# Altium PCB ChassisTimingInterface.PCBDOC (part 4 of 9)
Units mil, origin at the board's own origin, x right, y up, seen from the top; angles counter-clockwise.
Board outline 7007.87 x 4368.85 mil, 10 copper layers (Top Layer, Int1 (GND), Int2 (Sign), Int3 (Sign), Int4 (PWR), Int5 (GND), Int6 (Sign), Int7 (Sign), Int8 (GND), Bottom Layer), stack 54.89 mil thick; 537 components, 525 nets, 2288 pads, 1306 vias.
Unrouted connection lines stored in the file: 373.
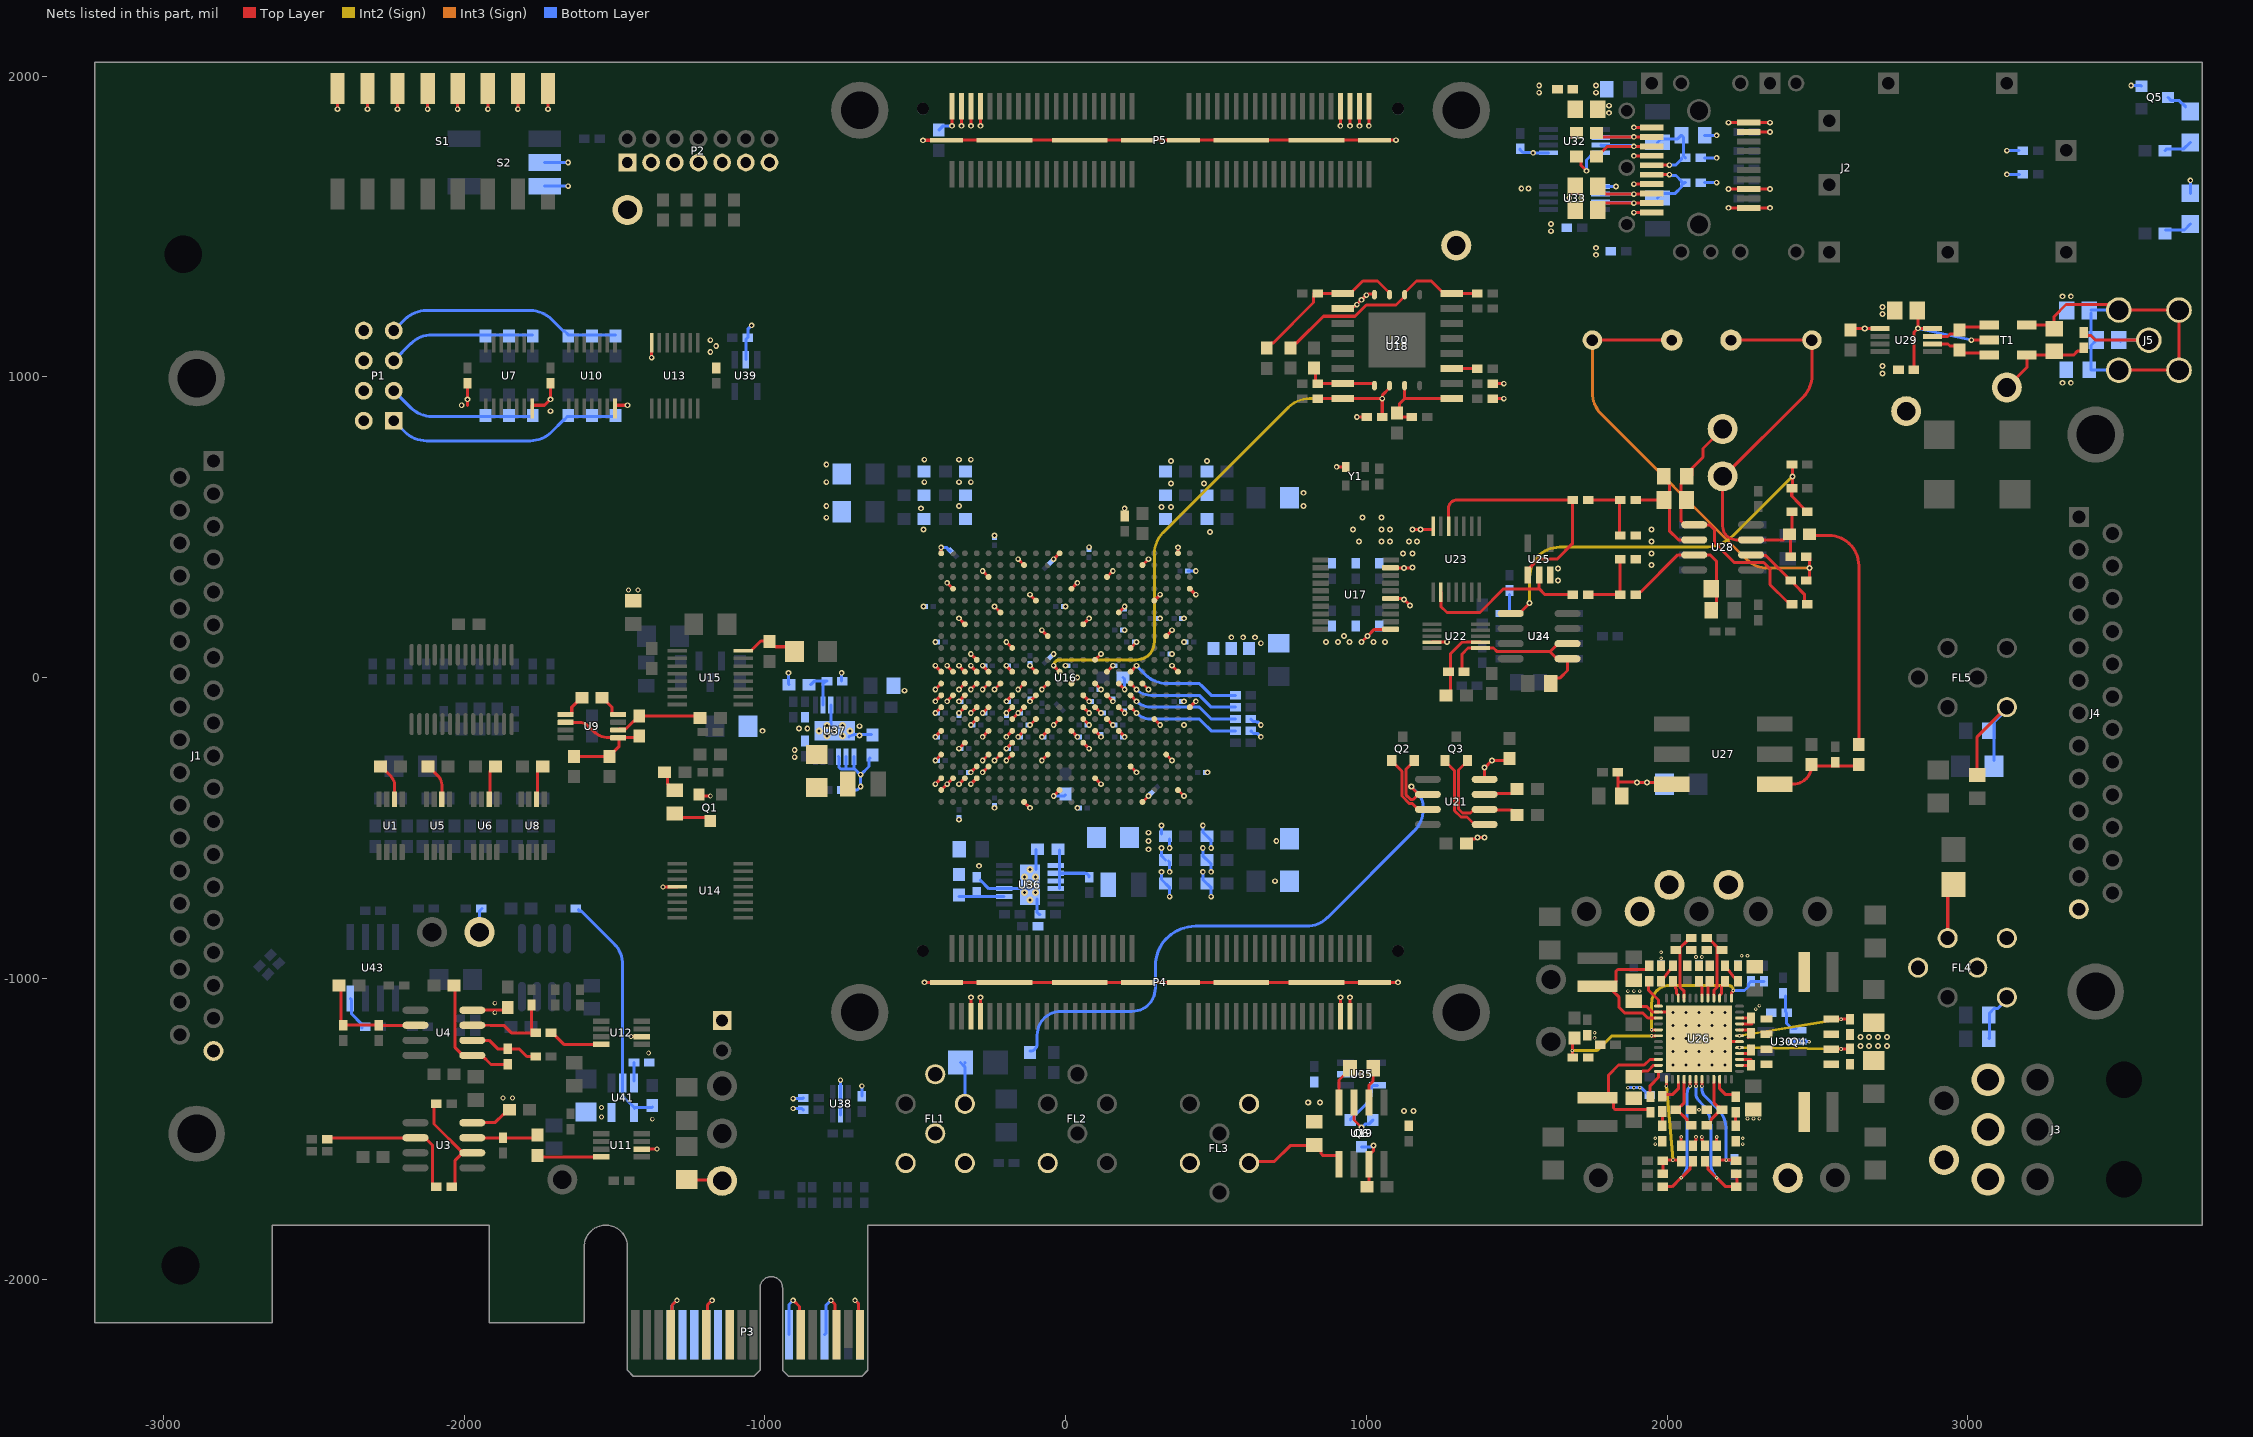
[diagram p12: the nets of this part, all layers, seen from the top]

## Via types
v1: diameter 19, hole 10, Top Layer to Bottom Layer, tented both sides, 667 vias
v2: diameter 20, hole 10, Top Layer to Bottom Layer, tented both sides, 248 vias
v3: diameter 16, hole 10, Top Layer to Bottom Layer, tented both sides, 191 vias
v4: diameter 12, hole 6, Top Layer to Bottom Layer, tented both sides, 85 vias
v5: diameter 19.68, hole 10, Top Layer to Bottom Layer, tented both sides, 50 vias
v6: diameter 17.72, hole 10, Top Layer to Bottom Layer, tented both sides, 19 vias
v7: diameter 19, hole 10, Top Layer to Bottom Layer, 15 vias
v8: diameter 23.62, hole 10, Top Layer to Bottom Layer, tented both sides, 14 vias
v9: diameter 20, hole 10, Top Layer to Bottom Layer, 11 vias
v10: diameter 16, hole 10, Top Layer to Bottom Layer, 3 vias
v11: diameter 22, hole 12, Top Layer to Bottom Layer, tented both sides, 2 vias
v12: diameter 19.02, hole 10, Top Layer to Bottom Layer, tented both sides, 1 vias

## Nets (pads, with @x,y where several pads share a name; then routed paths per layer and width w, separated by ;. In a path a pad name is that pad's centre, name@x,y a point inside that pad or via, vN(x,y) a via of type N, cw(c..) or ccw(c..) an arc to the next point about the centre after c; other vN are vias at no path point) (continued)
GND: C6.2 C12.2 C18.2 C23.2 C25.1 C26.1 C28.2 C29.2 C31.1 C32.1 C35.1 C37.1 C40.1 C41.2 C42.1 C43.2 C44.2 C45.1 C46.1 C51.1 C52.1 C53.2 C54.1 C57.1 C58.1 C59.2 C60.2 C68.2 C69.2 C70.1 C71.1 C74.2 C75.1 C76.2 C77.1 C78.2 C79.2 C80.2 C81.2 C84.1 C85.1 C86.1 C87.1 C88.1 C90.1 C92.1 C94.1 C95.1 C96.1 C97.1 C98.1 C99.1 C100.1 C101.1 C102.1 C103.1 C104.1 C105.1 C106.1 C107.1 C108.1 C109.1 C110.1 C111.1 C112.1 C113.1 C114.1 C115.1 C116.1 C117.1 C118.1 C119.1 C120.1 C121.1 C122.1 C123.1 C124.1 C125.1 C126.1 C127.1 C128.1 C129.1 C130.1 C131.2 C132.1 C133.2 C134.1 C135.2 C136.1 C137.1 C138.2 C139.2 C140.2 C141.1 C142.1 C143.1 C144.2 C145.2 C146.1 C147.1 C149.1 C150.1 C151.1 C152.1 C153.2 C155.1 C156.1 C157.2 C158.2 C159.2 C160.1 C161.1 C162.2 C163.2 C164.1 C165.1 C166.1 C167.1 C168.1 C169.2 C170.1 C171.1 C172.1 C173.2 C174.1 C175.2 C176.1 C177.1 C178.1 C179.1 C180.1 C181.1 C182.1 C183.1 C184.1 C185.1 C186.1 C187.1 C188.1 C189.1 C190.1 C191.1 C192.1 C195.2 C196.2 C197.1 C200.1 DS2.1 FL1.3 FL1.4 FL1.5 FL1.6 FL2.3 FL3.3 FL4.3 FL4.4 FL4.5 FL4.6 FL5.3 FR4.1 J1.19 J2.1 J2.3 J2.9 J2.10 J2.11 J2.14 J2.17 J2.20 J3.4 J3.5 J3.6 J4.13 P1.2 P1.4 P1.6 P1.8 P2.1 P2.3 P2.5 P2.7 P2.9 P2.11 P2.13 P3.A4 P3.A12 P3.A15 P3.A18 P3.B4 P3.B7 P3.B13 P3.B16 P3.B18 P4.5 P4.7 P4.73 P4.75 P4.81 P4.82 P4.83 P4.84 P4.85 P4.86 P4.87 P4.88 P5.2 P5.4 P5.6 P5.8 P5.74 P5.76 P5.78 P5.80 P5.81 P5.82 P5.83 P5.84 P5.85 P5.86 P5.87 P5.88 Q1.2 Q4.1 Q4.3 Q5.2 Q6.2 R28.2 R36.2 R45.2 R52.2 R53.2 R54.1 R57.2 R69.2 R70.2 R71.2 R73.1 R74.2 R75.2 R76.2 R80.2 R81.2 R93.2 R94.2 R98.2 R106.2 R107.2 R115.1 R116.1 R120.2 R123.1 R125.1 R127.1 R132.2 R133.2 R138.1 R139.1 R144.1 R147.1 R150.1 R151.1 R152.1 S1.1 S1.2 S1.3 S1.4 S1.5 S1.6 S1.7 S1.8 S2.3 S2.5 TP4.1 TP8.1 TP13.1 TP14.1 TP18.1 TP20.1 TP23.1 TP24.1 U7.7 U10.7 U11.6 U12.6 U13.7 U14.12 U16.A2 U16.A3 U16.A5 U16.A7 U16.A9 U16.A10 U16.A11 U16.A12 U16.A22 U16.AA2 U16.AA12 U16.AA22 U16.AB9 U16.AB19 U16.B3 U16.B10 U16.B12 U16.B19 U16.C3 U16.C6 U16.C9 U16.C10 U16.C11 U16.C12 U16.C16 U16.D3 U16.D4 U16.D8 U16.D9 U16.D11 U16.D12 U16.D13 U16.E4 U16.E5 U16.E7 U16.E9 U16.E11 U16.E12 U16.E20 U16.F5 U16.F11 U16.F17 U16.G5 U16.G6 U16.G7 U16.G8 U16.G9 U16.G10 U16.G12 U16.G14 U16.H1 U16.H7 U16.H9 U16.H11 U16.H21 U16.J8 U16.J10 U16.J12 U16.J18 U16.K5 U16.K7 U16.K11 U16.K15 U16.L2 U16.L8 U16.L22 U16.M7 U16.M11 U16.M19 U16.N6 U16.N8 U16.N9 U16.N10 U16.N16 U16.P3 U16.P7 U16.P9 U16.P11 U16.P13 U16.R8 U16.R10 U16.R12 U16.R20 U16.T7 U16.T9 U16.T11 U16.T17 U16.U4 U16.U14 U16.V1 U16.V11 U16.V21 U16.W8 U16.W18 U16.Y5 U16.Y15 U17.11 U17.15 U17.19 U18.10 U19.3 U20.4 U21.4 U22.9 U23.7 U25.3 U26.2 U26.11 U26.30 U26.49 U29.5 U30.2 U32.5 U33.5 U35.2 U36.9 U36.13 U37.9 U37.13 U38.2 U38.5 U39.2 W1.1 Y1.2 | length 14427.8
  Top Layer w10: v1(-2420.87,1889.76) S1.8@-2420.87,1958.66 ; v1(-2320.87,1889.76) S1.7@-2320.87,1958.66 ; v1(-2220.87,1889.76) S1.6@-2220.87,1958.66 ; v1(-2120.87,1889.76) S1.5@-2120.87,1958.66 ; v1(-2020.87,1889.76) S1.4@-2020.87,1958.66 ; -1988.19,905.51 C6.2@-1988.19,964.57 ; v1(-1920.87,1889.76) S1.3@-1920.87,1958.66 ; v1(-1820.87,1889.76) S1.2@-1820.87,1958.66 ; U7.7@-1773.62,894.69 -1773.62,904.61 -1772.72,905.51 -1732.28,905.51 v1(-1712.6,925.2) C12.2@-1712.6,968.5 ; v1(-1720.87,1889.76) S1.1@-1720.87,1958.66 ; U10.7@-1498.03,894.69 -1498.03,904.61 -1497.13,905.51 v1(-1456.69,905.51) ; v3(-1445.01,-1193.9) U12.6@-1409.45,-1193.9 ; U11.6@-1409.45,-1567.91 v3(-1358.27,-1567.91) ; U13.7@-1375.98,1113.19 -1375.98,1067.64 v1@-1375.27,1066.93 ; v3(-1338.58,-695.87) U14.12@-1290.35,-695.87 ; P3.B4@-1312.99,-2185.04 -1308.17,-2180.22 -1308.17,-2087.2 v6(-1291.58,-2070.62) ; Q1.2@-1218.5,-388.78 -1213.58,-393.7 v3(-1181.1,-393.7) ; P3.B7@-1194.88,-2185.04 -1190.06,-2180.22 -1190.06,-2085.73 v6(-1174.95,-2070.62) ; v6(-905.51,-2070.62) -884.74,-2091.39 -884.74,-2180.22 P3.B13@-879.92,-2185.04 ; v6(-780.02,-2070.62) -766.63,-2084.01 -766.63,-2180.22 P3.B16@-761.81,-2185.04 ; v6(-700.05,-2070.62) -687.89,-2082.78 -687.89,-2180.22 P3.B18@-683.07,-2185.04 ; v1(-468.6,-1013.39) v1(1105.7,-1013.39) ; v1(-433.07,-354.33) U16.A3@-413.39,-334.65 ; v1(-433.07,-275.59) U16.A5@-413.39,-255.91 ; v7(-433.07,-196.85) U16.A7@-413.39,-177.17 ; v1(-433.07,-118.11) U16.A9@-413.39,-98.43 ; v1(-433.07,-78.74) U16.A10@-413.39,-59.06 ; v1(-433.07,-39.37) U16.A11@-413.39,-19.68 ; v1(-433.07,39.37) U16.A12@-413.39,19.69 ; U16.A2@-413.39,-374.02 U16.B3@-374.02,-334.65 ; U16.A22@-413.39,413.39 v1(-413.39,433.07) ; P5.81@-395.47,1786.61 v1(-474.2,1786.61) v1(-474.2,1786.61) P5.88@1026.96,1786.61 P5.88@1026.96,1786.61 ; v1(-393.7,-78.74) U16.B10@-374.02,-59.06 ; v1(-393.7,39.37) U16.B12@-374.02,19.69 ; v1(-393.7,314.96) U16.B19@-374.02,295.28 ; v7(-377.15,1834.65) P5.2@-377.15,1899.4 ; v1(-354.33,-354.33) U16.C3@-334.65,-334.65 ; v1(-354.33,-236.22) U16.C6@-334.65,-216.54 ; v1(-354.33,-118.11) U16.C9@-334.65,-98.43 ; v1(-354.33,-78.74) U16.C10@-334.65,-59.06 ; v1(-354.33,-39.37) U16.C11@-334.65,-19.68 ; v1(-354.33,39.37) U16.C12@-334.65,19.69 ; v1(-354.33,196.85) U16.C16@-334.65,177.17 ; v1(-345.67,1834.65) P5.4@-345.67,1899.4 ; v1(-314.96,-354.33) U16.D3@-295.28,-334.65 ; v1(-314.96,-314.96) U16.D4@-295.28,-295.28 ; v1(-314.96,-157.48) U16.D8@-295.28,-137.8 ; v1(-314.96,-118.11) U16.D9@-295.28,-98.43 ; v1(-314.96,-39.37) U16.D11@-295.28,-19.68 ; v1(-314.96,39.37) U16.D12@-295.28,19.69 ; v1(-314.96,78.74) U16.D13@-295.28,59.06 ; P4.5@-314.17,-1126.17 v1(-314.17,-1062.99) ; v1(-314.17,1834.65) P5.6@-314.17,1899.4 ; P4.7@-282.67,-1126.17 v1(-282.67,-1062.99) ; v1(-282.67,1834.65) P5.8@-282.67,1899.4 ; v1(-275.59,-314.96) U16.E4@-255.91,-295.28 ; v1(-275.59,-275.59) U16.E5@-255.91,-255.91 ; v1(-275.59,-196.85) U16.E7@-255.91,-177.17 ; v1(-275.59,-118.11) U16.E9@-255.91,-98.43 ; v1(-275.59,-39.37) U16.E11@-255.91,-19.68 ; v1(-275.59,39.37) U16.E12@-255.91,19.69 ; v1(-275.59,354.33) U16.E20@-255.91,334.65 ; v1(-236.22,-275.59) U16.F5@-216.54,-255.91 ; v1(-236.22,-39.37) U16.F11@-216.54,-19.68 ; v1(-236.22,236.22) U16.F17@-216.54,216.54 ; v1(-196.85,-275.59) U16.G5@-177.17,-255.91 ; v1(-196.85,-236.22) U16.G6@-177.17,-216.54 ; v1(-196.85,-196.85) U16.G7@-177.17,-177.17 ; v1(-196.85,-118.11) U16.G9@-177.17,-98.43 ; v1(-196.85,-78.74) U16.G10@-177.17,-59.06 ; v1(-196.85,39.37) U16.G12@-177.17,19.69 ; v1(-196.85,118.11) U16.G14@-177.17,98.43 ; U16.G8@-177.17,-137.8 U16.H9@-137.8,-98.43 ; v1(-157.48,-196.85) U16.H7@-137.8,-177.17 ; v1(-157.48,-39.37) U16.H11@-137.8,-19.68 ; v1(-157.48,393.7) U16.H21@-137.8,374.02 ; U16.H1@-137.8,-413.39 -137.8,-414.52 -119.25,-433.07 v1(-118.11,-433.07) ; v1(-118.11,-157.48) U16.J8@-98.43,-137.8 ; v1(-118.11,-78.74) U16.J10@-98.43,-59.06 ; v1(-118.11,39.37) U16.J12@-98.43,19.69 ; v1(-118.11,275.59) U16.J18@-98.43,255.91 ; v1(-78.74,-275.59) U16.K5@-59.06,-255.91 ; v1(-78.74,-196.85) U16.K7@-59.06,-177.17 ; v1(-78.74,-39.37) U16.K11@-59.06,-19.68 ; v1(-78.74,157.48) U16.K15@-59.06,137.8 ; v1(-39.37,-393.7) U16.L2@-19.69,-374.02 ; v1(-39.37,-157.48) U16.L8@-19.69,-137.8 ; v1(-39.37,393.7) U16.L22@-19.69,413.39 ; U16.M7@19.69,-177.17 v1(39.37,-196.85) ; U16.M11@19.69,-19.68 v1(39.37,0) ; U16.M19@19.69,295.28 v1(39.37,314.96) ; U16.N6@59.06,-216.54 v1(78.74,-236.22) ; U16.N8@59.06,-137.8 v1(78.74,-157.48) ; U16.N9@59.06,-98.43 v1(78.74,-118.11) ; U16.N10@59.06,-59.06 v1(78.74,-78.74) ; U16.N16@59.06,177.17 v1(78.74,196.85) ; U16.P3@98.43,-334.65 v1(118.11,-354.33) ; U16.P7@98.43,-177.17 v1(118.11,-196.85) ; U16.P9@98.43,-98.43 v1(118.11,-118.11) ; U16.P11@98.43,-19.68 v1(118.11,-39.37) ; U16.P13@98.43,59.06 v1(118.11,78.74) ; U16.R8@137.8,-137.8 v1(157.48,-157.48) ; U16.R10@137.8,-59.06 v1(157.48,-78.74) ; U16.R12@137.8,19.69 v1(157.48,39.37) ; U16.R20@137.8,334.65 v1(157.48,354.33) ; U16.T7@177.17,-177.17 v1(196.85,-196.85) ; U16.T9@177.17,-98.43 v1(196.85,-118.11) ; U16.T11@177.17,-19.68 v1(196.85,-39.37) ; U16.T17@177.17,216.54 v1(196.85,236.22) ; R28.2@196.85,537.4 v1(196.85,562.99) ; U16.U4@216.54,-295.28 v1(236.22,-314.96) ; U16.U14@216.54,98.43 v1(236.22,118.11) ; U16.V1@255.91,-413.39 v1(275.59,-393.7) ; U16.V11@255.91,-19.68 v1(275.59,-39.37) ; U16.V21@255.91,374.02 v1(275.59,393.7) ; U16.W8@295.28,-137.8 v1(314.96,-157.48) ; U16.W18@295.28,255.91 v1(314.96,275.59) ; U16.Y5@334.65,-255.91 v1(354.33,-275.59) ; U16.Y15@334.65,137.8 v1(354.33,157.48) ; v1(354.33,39.37) U16.AA12@374.02,19.69 ; U16.AA2@374.02,-374.02 v1(393.7,-393.7) ; U16.AA22@374.02,413.39 v1(374.02,433.07) ; U16.AB9@413.39,-98.43 v1(433.07,-78.74) ; U16.AB19@413.39,295.28 v1(433.07,275.59) ; v1(901.57,700.79) Y1.2@933.07,700.79 ; v1(913.77,1834.65) 913.77,1898.44 cw(c915.12,1898.44) P5.74@914.16,1899.4 ; P4.73@914.16,-1126.17 v1(914.16,-1062.99) ; U18.10@921.26,1227.36 928.07,1234.17 960.08,1234.17 966.07,1240.16 v1(968.5,1240.16) v1(1000,1271.65) 1002.44,1271.65 1006.42,1275.64 1024.95,1275.64 U20.4@1027.36,1273.23 ; P4.75@945.66,-1126.17 v1(945.66,-1062.99) ; v1(945.66,1834.65) P5.76@945.66,1899.4 ; U19.3@959.25,-1413.39 958.94,-1413.7 958.94,-1470.75 v2(984.25,-1496.06) ; v1(968.5,866.14) R36.2@1001.97,866.14 ; v1(977.16,1834.65) P5.78@977.16,1899.4 ; v9(984.25,118.11) v9(1003.94,137.8) 1026.57,160.43 U17.11@1080.71,160.43 ; v1(1008.65,1834.65) P5.80@1008.65,1899.4 ; P5.88@1027.03,1786.68 v1@1098.96,1786.68 ; U17.15@1080.71,262.8 1081.33,262.18 1120.94,262.18 1121.36,261.76 1121.43,261.76 v9@1122.47,262.8 ; U17.19@1080.71,365.16 1152.56,365.16 v9(1153.05,365.65) ; v9@1125.98,259.8 v9(1145.67,240.16) ; v2(1153.54,492.13) U23.7@1220.47,492.13 ; U22.9@1218.5,118.11 v2(1267.72,118.11) ; C29.2@1332.68,-551.18 1347.36,-536.5 1362.37,-536.5 1367.37,-531.5 v2(1393.7,-531.5) ; U21.4@1393.7,-338.39 1393.7,-299.52 1417.32,-275.9 v2(1417.32,-275.59) 1474.41,-275.59 R45.2@1476.38,-273.62 ; C31.1@1420.07,977.36 v1(1457.48,977.36) ; C32.1@1420.08,927.36 v1(1457.48,927.36) ; C43.2@1889.76,-1327.75 1894.68,-1327.75 1912.32,-1310.11 1916.36,-1310.11 1918.18,-1308.29 1936.44,-1308.29 1955.36,-1289.37 U26.11@1961.69,-1289.37 ; C44.2@1889.76,-1075.78 1894.68,-1075.78 1912.13,-1093.23 1931.59,-1093.23 1950.57,-1112.2 U26.2@1971.46,-1112.2 ; v1(1889.76,1546.06) J2.20@1948.82,1546.06 ; v1(1889.76,1640.55) J2.17@1948.82,1640.55 ; v1(1889.76,1735.04) J2.14@1948.82,1735.04 ; v1(1889.76,1829.53) J2.11@1948.82,1829.53 ; U26.2@1981.22,-1112.19 U26.49@2017.72,-1112.19 ; U26.49@2019.68,-1287.39 U26.49@2106.29,-1200.79 ; v5(2019.68,-1114.17) v5(2106.3,-1200.79) ; R71.2@2047.24,-1557.09 v4(2047.24,-1527.31) ; R73.1@2086.61,-1557.09 2095.39,-1548.31 2095.39,-1539.64 2096.52,-1538.51 v4(2096.52,-1527.31) ; v4(2116.14,-1527.56) 2116.14,-1538.51 2117.2,-1539.58 2117.2,-1548.31 R74.2@2125.98,-1557.09 ; R81.2@2165.35,-1557.09 v4(2165.35,-1527.56) ; v1(2204.72,1561.81) v1(2342.52,1561.81) ; v1(2204.72,1624.8) v1(2342.52,1624.8) ; v1(2204.72,1845.28) v1(2342.52,1845.28) ; U26.30@2241.14,-1210.63 2130.04,-1210.63 cw(c2130.04,-1177.06) U26.49@2106.3,-1200.8 ; J2.9@2271.65,1813.78 v1(2342.52,1813.78) ; C68.2@2598.43,1160.43 U29.5@2708.86,1160.43 ; v2(2657.48,1161.42) ccw(c2659.86,1163.79) v2@2659.86,1160.43 ; C74.2@3031.5,-323.82 3031.5,-196.85 FL5.3@3129.92,-98.43
  Bottom Layer w10: S2.3@-1732.28,1633.86 v1(-1653.54,1633.86) ; S2.5@-1732.28,1712.6 v1(-1653.54,1712.6) ; P3.A4@-1312.99,-2185.04 -1308.17,-2180.22 -1308.17,-2087.2 v6(-1291.58,-2070.62) ; U39.2@-1062.99,1057.09 -1062.99,1124.02 -1056.49,1130.52 -1056.49,1158.31 v1(-1043.31,1171.5) ; v1(-921.26,15.75) -921.26,-21.65 C197.1@-919.29,-23.62 ; P3.A12@-919.29,-2185.04 -919.29,-2084.4 v6(-905.51,-2070.62) ; v6(-905.51,-1433.07) -875.98,-1433.07 C195.2@-872.05,-1437.01 ; v6(-905.51,-1400.13) -904.38,-1399 -873.41,-1399 C196.2@-872.05,-1397.64 ; P3.A15@-801.18,-2185.04 -796.36,-2180.22 -796.36,-2086.96 v6(-780.02,-2070.62) ; U37.9@-780.51,-91.17 -780.51,-164.37 v8(-767.72,-177.17) ; U38.5@-748.03,-1454.72 v6(-748.03,-1338.58) ; R150.1@-744.09,-11.81 v1(-744.09,15.75) ; U37.13@-720.47,-196.85 cw(c-703.84,-213.48) -703.84,-189.96 v1@-688.98,-189.96 ; v6(-700.05,-2070.62) -687.89,-2082.78 -687.89,-2180.22 P3.A18@-683.07,-2185.04 ; v1@-685,-188.59 C192.1@-645.63,-188.59 ; R147.1@-677.17,-1391.73 v6(-677.17,-1358.27) ; C184.1@-421.26,1820.08 -406.69,1834.65 v7(-377.15,1834.65) ; v1(-413.39,433.07) -396.31,433.07 -384.5,421.26 C179.1@-381.89,421.26 ; R144.1@-283.46,-673.23 -254.92,-701.77 U36.9@-204.11,-701.77 -125,-701.77 cw(c-125,-704.72) U36.13@-122.05,-704.72 ; C155.1@-121.91,-78.88 v1@-118.11,-82.68 ; C155.1@-119.23,-77.63 v1(-118.11,-78.74) ; U36.13@-98.43,-637.8 -97.44,-636.81 C150.1@-97.44,-570.87 ; U36.13@-94.49,-736.22 -94.49,-777.56 ccw(c-84.65,-777.56) R138.1@-84.65,-787.4 ; v1(-39.37,-393.7) -3.94,-393.7 C147.1@0,-389.76 ; C130.1@190.94,0 196.85,-5.91 v1(196.85,-39.37) ; v1(318.9,-645.67) 318.9,-671.26 346.46,-698.82 v1(346.46,-728.35) ; v1(318.9,-566.93) 318.9,-592.52 C118.1@332.68,-606.3 ; C119.1@318.9,-519.68 v1(318.9,-492.13) ; C118.1@342.52,-610.24 346.46,-614.17 v1(346.46,-645.67) ; v1(346.46,-566.93) C119.1@346.46,-536.42 ; C116.1@406.69,354.33 v1(433.07,354.33) ; v1(456.69,-645.67) 456.69,-671.26 484.25,-698.82 v1(484.25,-728.35) ; v1(456.69,-566.93) 456.69,-592.52 484.25,-620.08 v1(484.25,-645.67) ; v1(456.69,-492.13) 456.69,-513.78 484.25,-541.34 v1(484.25,-566.93) ; R132.2@616.14,-177.17 624.92,-185.94 634.31,-185.94 634.72,-186.35 639.25,-186.35 649.61,-196.71 v1(649.61,-196.85) ; R133.2@616.14,-137.8 624.92,-146.57 634.15,-146.57 634.72,-147.14 639.25,-147.14 v1@649.59,-157.48 ; U35.2@931.1,-1318.9 v2(984.25,-1318.9) ; v2(984.25,-1496.06) 995.46,-1484.86 1008.25,-1484.86 Q6.2@1021.65,-1471.46 ; C92.1@1511.81,1757.87 1511.81,1754.44 1520.59,1745.66 1554.54,1745.66 v1(1555.12,1745.08) U32.5@1606.5,1745.08 ; U33.5@1779.33,1632.87 v1(1830.71,1632.87) ; v4(1870.08,-1363.18) v4(1909.45,-1363.18) 1909.83,-1363.56 1914.74,-1363.56 1938.98,-1387.8 R123.1@1942.91,-1387.8 ; C84.1@2125,1645.67 v1(2165.35,1645.67) ; C85.1@2125,1728.35 v1(2165.35,1728.35) ; C86.1@2125,1803.15 v1(2165.35,1803.15) ; v4(2397.64,-1210.62) U30.2@2435.04,-1210.63 v4(2472.44,-1210.64) ; C78.2@3069.88,-1200.78 3072.83,-1197.82 3072.83,-1115.25 3087.52,-1100.56 3099.81,-1100.56 3129.92,-1070.45 FL4.3@3129.92,-1062.99 ; C77.1@3086.61,-275.59 3086.61,-177.17 3087.52,-176.26 3087.52,-148.28 3129.92,-105.88 FL5.3@3129.92,-98.43 ; v1(3129.92,1673.23) R107.2@3171.26,1673.23 ; v1(3129.92,1751.97) C76.2@3170.28,1751.97 ; v1@3547.24,1968.5 3575.79,1968.5 Q5.2@3577.76,1966.54 ; DS2.1@3740.16,1610.24 v1(3740.16,1653.54)
  other v1: 696.85,-677.17 275.59,-570.87 275.59,-543.31 700.79,-543.31 275.59,-515.75 -354.33,-472.44 -236.22,-433.07 39.37,-433.07 -393.7,-354.33 472.44,-314.96 -900.59,-264.49 -900.59,-240.87 -685.04,-192.91 -1007.87,-177.17 -885.83,-169.29 -858.27,-169.29 -685.04,-161.42 393.7,-157.48 649.61,-157.48 -157.48,-118.11 393.7,-78.74 -535.43,-43.31 0,39.37 -39.37,78.74 354.33,78.74 649.61,114.17 -433.07,118.11 393.7,118.11 551.18,133.86 590.55,133.86 629.92,133.86 196.85,157.48 314.96,196.85 393.7,196.85 -472.44,236.22 0,236.22 78.74,433.84 -236.22,472.44 480.31,484.25 -472.44,492.13 -795.28,531.5 -480.32,562.99 318.9,566.93 350.39,566.93 -795.28,570.87 791.34,570.87 791.34,614.17 350.39,645.67 460.63,645.67 -469.52,649.61 350.39,720.47 470.47,720.47 -469.52,724.41 -1712.6,885.83 -2007.87,905.51 -1988.19,925.2 3314.96,980.32 3342.52,980.32 -1375.98,1063.48 -1181.1,1082.68 -1161.42,1102.36 -1181.1,1122.05 984.25,1255.91 3314.96,1267.72 3342.52,1267.72 1763.78,1405.51 1763.78,1429.13 1614.17,1484.25 1614.17,1507.87 1675.05,1594.36 1714.42,1594.36 1515.75,1625.98 1539.37,1625.98 1099.02,1786.74 1807.09,1877.95 1807.09,1901.57 1574.8,1944.88 1763.78,1944.88 1574.8,1968.5 1763.78,1968.5 3543.31,1968.5
  other v2: 1125.98,-1440.94 1157.48,-1440.94 807.09,-1413.39 846.46,-1413.39 2672.24,-1225.38 2701.77,-1225.38 2642.72,-1224.71 2731.3,-1224.46 2642.72,-1195.86 2672.24,-1195.86 2701.77,-1195.86 2731.3,-1195.86 1370.08,-531.5 1393.7,-299.21 866.14,118.11 905.51,118.11 944.88,118.11 1023.62,118.11 1062.99,118.11 925.2,137.8 1637.8,322.83 1637.8,362.2 1948.82,374.02 1122.05,413.39 1153.54,413.39 1948.82,413.39 976.38,452.76 1051.18,452.76 1078.74,452.76 1141.73,452.76 1169.29,452.76 1948.82,452.76 956.69,492.13 1051.18,492.13 1078.74,492.13 1181.1,492.13 1948.82,492.13 988.19,531.5 1051.18,531.5 2716.54,1011.81 2716.54,1035.43 2716.54,1208.66 2716.54,1232.28
  other v3: -1452.76,291.34 -1421.26,291.34
  other v4: 1960.63,-1551.18 2251.97,-1551.18 1960.63,-1531.5 2251.97,-1531.5 2267.72,-1466.54 2287.4,-1466.54 2307.09,-1466.54 2106.3,-1437.01 1889.76,-1363.18 1759.35,-1198.06 1759.35,-1181.09 2295.28,-1102.36 2307.09,-1090.55 1870.08,-1042.39 1889.76,-1042.39 1909.45,-1042.39 1980.32,-933.07 2096.46,-929.13 2116.14,-929.13 2248.03,-925.2 2267.72,-925.2 1980.32,-913.39
  other v5: 2019.68,-1287.4 2062.99,-1287.4 2106.3,-1287.4 2149.61,-1287.4 2192.91,-1287.4 2019.68,-1244.09 2062.99,-1244.09 2106.3,-1244.09 2149.61,-1244.09 2192.91,-1244.09 2019.68,-1200.79 2062.99,-1200.79 2149.61,-1200.79 2192.91,-1200.79 2019.68,-1157.48 2062.99,-1157.48 2106.3,-1157.48 2149.61,-1157.48 2192.91,-1157.48 2062.99,-1114.17 2106.3,-1114.17 2149.61,-1114.17 2192.91,-1114.17
  other v7: -354.33,570.87 -795.28,649.61 -354.33,649.61 -314.96,649.61 -795.28,708.66 -354.33,724.41 -314.96,724.41
  other v8: -118.11,-740.16 -135.83,-714.57 -100.39,-714.57 -118.11,-688.98 -135.83,-663.39 -100.39,-663.39 -118.11,-637.8 -793.31,-194.88 -742.13,-194.88 -818.9,-177.17 -716.54,-177.17 -793.31,-159.45 -742.13,-159.45
  other v9: 1125.98,259.84 1125.98,365.16
  other v12: -287.4,-625.98
INIT: R135.1 U16.U12 | length 393
  Top Layer w10: U16.U12@216.54,19.69 v1(236.22,39.37)
  Bottom Layer w10: v1(236.22,39.37) 265.99,9.6 ccw(c336.7,80.32) 336.7,-19.68 444.88,-19.68 452.76,-27.56 484.25,-59.06 R135.1@564.96,-59.06
JTAG1: P3.B9
JTAG2: P3.A5
JTAG3: P3.A6
JTAG4: P3.A7
JTAG5: P3.A8
M0: R134.1 U16.U11 | length 378.1
  Top Layer w10: U16.U11@216.54,-19.68 v1(236.22,-39.37)
  Bottom Layer w10: v1(236.22,-39.37) ccw(c283.74,8.15) 283.74,-59.06 444.88,-59.06 452.76,-66.93 484.25,-98.43 R134.1@564.96,-98.43
M1: R133.1 U16.U10 | length 378.1
  Top Layer w10: U16.U10@216.54,-59.06 v1(236.22,-78.74)
  Bottom Layer w10: v1(236.22,-78.74) ccw(c283.74,-31.22) 283.74,-98.43 444.88,-98.43 452.76,-106.3 484.25,-137.8 R133.1@564.96,-137.8
M2: R132.1 U16.U9 | length 378.1
  Top Layer w10: U16.U9@216.54,-98.43 v1(236.22,-118.11)
  Bottom Layer w10: v1(236.22,-118.11) ccw(c283.74,-70.59) 283.74,-137.8 444.88,-137.8 452.76,-145.67 484.25,-177.17 R132.1@564.96,-177.17
MON: C66.2 R90.2 R91.1 U24.5 | length 1366.9
  Top Layer w10: U24.5@1480.32,212.8 1508.12,212.8 1518.62,223.29 1518.62,223.35 v2(1543.31,248.03) ; C66.2@2415.35,708.66 2417.32,706.69 2417.32,631.89 R91.1@2415.35,629.92 2414.77,607.2 2414.69,603.89 2464.72,551.23 R90.2@2466.54,551.18
  Int2 (Sign) w10: v2(1543.31,248.03) 1543.31,333.66 cw(c1643.31,333.66) 1643.31,433.66 2124.52,433.66 ccw(c2124.52,571.68) 2222.12,474.09 v2(2417.32,669.29)
N5V: C9.1 C10.1 C205.1 C208.2 R181.1 TP2.1 U3.4 U4.4 U41.5 | length 352.5
  Top Layer w10: U3.4@-1972.44,-1480.12 -1897.44,-1480.12 -1869.02,-1451.69 -1865.08,-1451.69 -1854.33,-1440.95 C9.1@-1854.33,-1425.2 ; U4.4@-1972.44,-1106.1 -1970.98,-1104.64 -1857.59,-1104.64 C10.1@-1854.33,-1101.38
  Bottom Layer w10: TP2.1@-1948.82,-846.46 -1948.82,-776.5 R181.1@-1940.04,-767.72
  other v3: -1543.31,-1460.63 -1543.31,-1429.13 -1870.08,-1397.64 -1838.58,-1397.64 -1385.83,-1248.03 -1897.64,-1114.17 -1897.64,-1082.68
N12V: C20.2 C203.2 FL3.2 R160.1 TP5.1 U41.2 U41.4 | length 923
  Top Layer w10: C20.2@-1265.75,-1671.26 -1143.7,-1671.26 TP5.1@-1141.73,-1673.23
  Bottom Layer w10: R160.1@-1620.08,-771.65 -1615.24,-776.5 -1609.33,-776.5 -1501.73,-884.1 cw(c-1572.44,-954.81) -1472.44,-954.81 -1472.44,-1391.92 -1458.22,-1406.14 -1457.05,-1406.14 -1433.07,-1430.12 U41.4@-1433.07,-1433.07 ; U41.4@-1433.07,-1429.13 -1375,-1429.13 C203.2@-1374.02,-1428.15
  other v3: -1374.02,-1468.5
NetC1_2: C1.2 R3.2 R4.1 U4.6 | length 372.3
  Top Layer w10: R3.2@-2419.29,-1023.62 -2409.45,-1033.46 -2409.45,-1142.8 -2402.91,-1149.33 C1.2@-2401.85,-1149.33 ; C1.2@-2401.57,-1155.51 R4.1@-2283.46,-1155.51 ; R4.1@-2282.09,-1156.1 U4.6@-2161.42,-1156.1
NetC8_1: C8.1 R15.2 U3.3 | length 218.5
  Top Layer w10: U3.3@-1972.44,-1530.12 -1770.59,-1530.12 -1762.8,-1522.32 R15.2@-1762.8,-1516.73
NetC11_2: C11.2 R14.2 U4.3 | length 308.6
  Top Layer w8: -1928.33,-1156.1 -1911.42,-1156.1
  Top Layer w10: U4.3@-1972.44,-1156.1 -1928.33,-1156.1 ; -1911.42,-1156.1 -1867.62,-1156.1 -1842.62,-1181.1 R14.2@-1775.59,-1181.1 ; R14.2@-1775.59,-1188.98 R14.2@-1775.59,-1181.1 ; C11.2@-1775.59,-1101.38 R14.2@-1775.59,-1181.1 ; R14.2@-1761.81,-1181.1 R14.2@-1775.59,-1181.1
NetC24_2: C24.2 FR2.1 U15.16 | length 198
  Top Layer w10: U15.16@-1071.85,89.57 -1070.94,90.47 -1044.37,90.47 -1013.08,121.76 -985.83,121.76 C24.2@-984.25,120.19 ; C24.2@-984.25,118.22 -969.57,103.53 -964.71,103.53 -963.71,102.53 -905.68,102.53 FR2.1@-897.64,94.49
NetC25_2: C25.2 C192.2 L1.1 R149.2 U37.1 U37.2 U37.3 | length 375.2
  Bottom Layer w10: U37.3@-754.92,-263.17 -752.9,-265.19 -752.9,-298.35 -747.04,-304.21 -728.03,-304.21 ; R149.2@-742.13,-374.02 -692.63,-374.02 -681.1,-362.48 v1(-681.1,-322.83) ; U37.2@-729.33,-263.17 -729.33,-302.91 -728.03,-304.21 ; -703.74,-304.21 U37.1@-703.74,-263.17 ; C192.2@-649.61,-266.73 -653.54,-270.67 -653.54,-295.28 v1(-681.1,-322.83) ; -728.03,-304.21 -701.14,-304.21 -682.52,-322.83 v1(-681.1,-322.83)
  other v1: -681.1,-362.2
NetC26_2: C26.2 FL3.1 U19.5 | length 341.5
  Top Layer w10: FL3.1@610.24,-1614.17 615.51,-1608.9 694.25,-1608.9 746.88,-1556.27 824.64,-1556.27 C26.2@826.77,-1554.13 ; C26.2@848.43,-1570.87 849.33,-1571.77 849.33,-1582.72 855.19,-1588.58 902.44,-1588.58 909.25,-1595.39 U19.5@909.25,-1618.11
NetC27_1: C27.1 U19.4 | length 130.8
  Top Layer w10: U19.4@909.25,-1413.39 909.25,-1338.29 925.77,-1321.77 928.23,-1321.77 945.87,-1304.13 C27.1@945.87,-1299.21
NetC27_2: C27.2 U19.2 | length 119.7
  Top Layer w10: U19.2@1009.25,-1413.39 1009.25,-1355.2 1022.52,-1341.93 1022.52,-1299.33 C27.2@1022.64,-1299.21
NetC30_2: C30.2 R41.1 U22.2 | length 265.4
  Top Layer w10: C30.2@1264.72,-59.06 1279.41,-44.37 1279.41,13.9 R41.1@1273.62,19.69 1279.47,25.53 1279.47,78.68 1318.9,118.11 U22.2@1379.92,118.11
NetC34_1: C34.1 R41.2 U22.1 U24.1 U24.2 | length 593.3
  Top Layer w10: R41.2@1324.8,19.69 1318.9,25.59 1318.9,78.74 1338.58,98.43 U22.1@1379.92,98.43 1422.85,98.43 1435.35,85.93 1610.93,85.93 ; C34.1@1629.92,-1.61 1630.83,-0.7 1644.97,-0.7 1669.29,23.62 U24.1@1669.29,62.8 1634.11,62.8 1627.3,69.61 1627.24,69.61 1610.93,85.93 ; U24.2@1669.29,112.8 1637.8,112.8 1610.93,85.93
NetC35_2: C35.2 R55.1 R56.1 R57.1 U32.4 | length 156.2
  Top Layer w10: R55.1@1696.85,1732.28 1698.52,1732.28 1713.21,1717.6 1713.21,1704.12 v1(1732.28,1685.04)
  Bottom Layer w10: v1(1732.28,1685.04) 1732.28,1720.87 1756.5,1745.08 U32.4@1779.72,1745.08
NetC36_1: C36.1 C47.1 C65.2 R89.2 | length 1486.9
  Top Layer w10: C36.1@1751.97,1122.05 C47.1@2015.75,1122.05 ; R89.2@2474.41,329.73 2474.41,392.72 C65.2@2475.39,393.7
  Int3 (Sign) w10: C36.1@1751.97,1122.05 1751.97,946.99 ccw(c1851.97,946.99) 1781.26,876.28 2264.58,392.96 ccw(c2335.29,463.67) 2335.29,363.67 v2@2478.35,363.67
  other v2: 2474.41,363.67
NetC36_2: C36.2 C47.2 C65.1 R87.2 R90.1 TP16.1 U28.7 | length 1411.1
  Top Layer w10: C47.2@2212.6,1122.05 C36.2@2481.97,1122.05 2481.97,1003.7 cw(c2381.97,1003.7) 2452.68,932.99 2188.98,669.29 ccw(c2188.98,665.35) 2185.04,665.35 2185.04,503.11 ccw(c2230.08,503.11) 2230.08,458.07 2387.2,458.07 2401.57,472.44 R87.2@2403.54,472.44 ; R87.2@2405.51,478.35 2415.35,488.19 R90.1@2415.35,551.18 ; R87.2@2407.48,476.38 2411.42,472.44 C65.1@2411.42,401.57
NetC38_2: C38.2 C39.2 FR3.1 U27.6 | length 360.8
  Top Layer w10: C39.2@1836.61,-314.96 1836.61,-347.93 ; C38.2@1849.41,-393.7 1836.61,-380.91 1836.61,-347.93 ; U27.6@2015.75,-354.33 2009.84,-348.43 v2(1899.61,-348.43) 1899.11,-347.93 1836.61,-347.93
  Bottom Layer w10: v2(1899.61,-348.43) 1986.22,-348.43 FR3.1@1992.13,-354.33
  other v9: 1933.01,-348.43
NetC41_1: C41.1 R51.2 R60.1 | length 202.4
  Top Layer w10: R51.2@1750,590.55 R60.1@1832.68,590.55 ; C41.1@1844.49,472.44 1842.52,474.41 1842.52,588.58 R60.1@1844.49,590.55
NetC42_2: C42.2 R50.2 R59.1 | length 201
  Top Layer w10: R50.2@1750,275.59 1828.74,275.59 R59.1@1831.69,272.64 ; R59.1@1844.49,275.59 C42.2@1844.49,393.7
NetC48_1: C48.1 L3.1 U26.3 | length 408.3
  Top Layer w10: C48.1@1946.85,-961.6 1938.06,-970.4 1836.37,-970.4 1830.51,-976.26 1830.51,-1011.69 1827.11,-1015.1 1820.05,-1015.1 1820.05,-1022.16 1810.03,-1032.18 1810.03,-1040.28 1818.2,-1040.28 1841,-1063.08 1841,-1096.64 1860.14,-1115.78 1920.21,-1115.78 1936.31,-1131.88 U26.3@1961.69,-1131.88
NetC48_2: C48.2 U26.1 | length 94.5
  Top Layer w10: C48.2@1937.99,-1011.81 1937.99,-1038.56 1971.46,-1072.03 U26.1@1971.46,-1092.44
NetC49_1: C49.1 L2.1 U26.10 | length 483.1
  Top Layer w10: L2.1@1768.58,-1397.68 1807.79,-1397.68 1822.09,-1411.97 1822.09,-1430.83 1827.94,-1436.68 1936.68,-1436.68 C49.1@1944.88,-1444.88 ; L2.1@1829.39,-1410.85 1829.39,-1406.68 1806.1,-1383.39 1806.1,-1321.2 1838.77,-1288.53 1924.28,-1288.53 1943.13,-1269.68 U26.10@1961.69,-1269.68
NetC49_2: C49.2 U26.12 | length 89.1
  Top Layer w10: C49.2@1943.9,-1386.8 1943.9,-1356.73 1971.46,-1329.17 U26.12@1971.46,-1309.13
NetC50_1: C50.1 R64.2 R88.1 TP17.1 U28.1 | length 884.3
  Top Layer w10: C50.1@2065.94,669.29 2065.94,664.37 2047.24,645.67 2047.24,590.55 2047.3,590.49 2047.3,520.74 2059.8,508.24 2059.8,508.07 2141.54,508.07 2157.48,492.13 2157.48,448.82 2223.27,383.03 2321.64,383.03 2342.52,362.15 2342.52,309.06 2398.7,252.87 2402.64,252.87 2403.54,251.97 R88.1@2403.54,244.09 ; C50.1@2082.68,673.23 2083.58,674.13 2083.58,696.7 2119.61,732.73 2119.61,761.34 TP17.1@2185.04,826.77
NetC50_2: C50.2 R60.2 R64.1 U28.2 | length 398.1
  Top Layer w10: R60.2@1907.48,590.55 R64.1@1990.16,590.55 ; C50.2@1989.17,669.29 2006.81,651.65 2006.81,641.88 2007.81,640.87 R64.1@2007.81,594.55 ; 2007.87,625.98 2007.87,488.19 2037.99,458.07 U28.2@2090.55,458.07
NetC51_2: C51.2 R66.1 | length 64.6
  Top Layer w10: C51.2@1980.32,-1009.84 R66.1@2019.68,-958.66
NetC52_2: C52.2 R65.1 | length 42.3
  Top Layer w10: R65.1@1984.19,-1437.98 1984.19,-1480.24 C52.2@1984.25,-1480.3
NetC54_2: C54.2 U26.42 | length 45.1
  Top Layer w10: C54.2@2107.27,-1014.75 2115.08,-1022.56 2115.08,-1027.42 2116.08,-1028.42 U26.42@2116.08,-1056.18
NetC56_2: C56.2 R59.2 R79.1 U28.3 | length 505.2
  Top Layer w10: R59.2@1907.48,283.46 1908.39,284.37 1912.32,284.37 2036.02,408.07 2143.11,408.07 2165.35,385.83 R79.1@2165.35,312.99 ; R79.1@2147.64,295.28 R79.1@2165.35,312.99 ; C56.2@2165.35,224.41 R79.1@2165.35,312.99
NetC57_2: C57.2 R86.1 | length 43.3
  Top Layer w10: C57.2@2228.35,-1482.28 R86.1@2228.35,-1438.98
NetC58_2: C58.2 R82.1 | length 65.8
  Top Layer w10: R82.1@2192.91,-958.66 C58.2@2234.25,-1009.83
NetC61_1: C61.1 U26.28 | length 50.6
  Top Layer w10: U26.28@2241.14,-1249.99 U26.28@2241.27,-1250.12 ; U26.28@2250.9,-1249.99 C61.1@2283.53,-1249.99 ; C61.1@2273.75,-1224.46 2273.75,-1228.4 C61.1@2283.53,-1238.18
NetC61_2: C61.2 L4.1 Q4.7 Q4.8 U26.26 U26.27 | length 57.3
  Top Layer w10: U26.26@2250.9,-1289.36 C61.2@2279.59,-1289.36 ; U26.27@2250.9,-1269.68 2279.56,-1269.68
NetC62_1: C62.1 U26.32 | length 56.3
  Top Layer w10: U26.32@2241.14,-1171.26 U26.32@2241.2,-1171.19 ; U26.32@2250.9,-1171.25 C62.1@2289.37,-1171.25 ; C62.1@2269.81,-1196.78 2279.59,-1187 C62.1@2279.59,-1183.06
NetC62_2: C62.2 L5.1 Q4.5 Q4.6 U26.33 U26.34 | length 60.3
  Top Layer w10: U26.33@2250.9,-1151.56 2282.54,-1151.56 ; U26.34@2250.9,-1131.88 C62.2@2279.59,-1131.88
NetC67_1: C67.1 R92.1 R95.1 U27.1 | length 323.4
  Top Layer w10: U27.1@2358.27,-354.33 2419.29,-354.33 ccw(c2419.29,-293.31) 2480.31,-293.31 2643.7,-293.31 cw(c2643.7,-295.28) R95.1@2645.67,-295.28
NetC71_2: C71.2 R98.1 T1.2 U29.4 | length 483.9
  Top Layer w10: C71.2@2820.87,1031.5 2820.87,1147.64 v1(2834.65,1161.42) ; R98.1@2832.68,1220.47 2834.65,1218.5 v1(2834.65,1161.42) ; U29.4@2882.09,1160.43 2881.1,1161.42 v1(2834.65,1161.42) ; v1(3011.81,1122.05) T1.2@3070.87,1122.05
  Bottom Layer w10: v1(2834.65,1161.42) v1(3011.81,1122.05)
NetC75_2: C75.2 J5.2 R101.1 R105.1 R106.1 T1.4 | length 1341.1
  Top Layer w10: T1.4@3195.87,1172.05 R101.1@3287.4,1172.05 ; R101.1@3287.4,1159.45 R101.1@3287.4,1172.05 ; J5.2@3491.58,1235.67 3468.44,1235.67 3463.96,1240.16 3326.77,1240.16 3287.4,1200.79 R101.1@3287.4,1172.05 ; J5.2@3502.36,1022.05 J5.2@3699.29,1022.05 ; J5.2@3502.36,1222.05 3696.99,1222.05 cw(c3696.99,1216.67) J5.2@3700.79,1220.47 ; J5.2@3702.36,1222.05 3702.36,1029.32 ccw(c3710.43,1029.32) J5.2@3704.72,1023.62
  Bottom Layer w10: R106.1@3409.45,1212.6 3409.45,1139.76 R105.1@3427.17,1122.05 3409.45,1104.33 3409.45,1022.05 J5.2@3502.36,1022.05 ; R106.1@3409.45,1222.05 J5.2@3502.36,1222.05
NetC81_1: C81.1 R108.1 U30.1 | length 130.7
  Bottom Layer w10: R108.1@2393.7,-1059.06 2393.7,-1110.72 C81.1@2397.64,-1114.66 2397.64,-1149.65 2415.31,-1167.32 U30.1@2428.75,-1167.32
NetC84_2: C84.2 J2.16 L6.1 | length 228.6
  Top Layer w10: J2.16@1948.82,1672.05 v1(2007.87,1672.05)
  Bottom Layer w10: L6.1@1968.5,1594.49 1984.25,1610.24 2027.56,1610.24 2048.31,1630.98 2048.31,1636.89 2057.09,1645.67 C84.2@2061.02,1645.67 ; v1@2008.91,1670.33 2012.03,1670.33 2013.13,1669.23 2029.59,1669.23 2048.23,1650.59 C84.2@2048.23,1645.67
NetC85_2: C85.2 C86.2 J2.15 L7.1 | length 280.7
  Top Layer w10: J2.15@1948.82,1703.54 v1(2007.87,1703.54)
  Bottom Layer w10: L7.1@1968.5,1779.53 1980.31,1791.34 2035.43,1791.34 C86.2@2047.24,1803.15 ; v1@2007.87,1704.72 2007.94,1704.79 2029.59,1704.79 2048.23,1723.43 C85.2@2048.23,1728.35 ; C86.2@2048.23,1803.15 2055.12,1796.26 2055.12,1734.25 C85.2@2061.02,1728.35
NetC93_2: C93.2 U34.4 | length 65.4
  Bottom Layer w10: U34.4@1472.44,212.8 1476.38,216.73 C93.2@1476.38,276.57
NetC129_2: C129.2 C150.2 L8.1 R136.2 U36.1 U36.2 U36.3 U36.4 | length 233
  Bottom Layer w10: U36.4@-19.69,-700.79 U36.2@-19.69,-650.59 ; C150.2@-19.69,-573.82 U36.2@-19.69,-650.59 ; R136.2@78.74,-663.39 78.74,-659.45 69.96,-650.67 64.18,-650.67 64.1,-650.59 U36.2@-19.69,-650.59
NetC176_2: C176.2 R144.2 U36.8 | length 149.2
  Bottom Layer w10: C176.2@-353.35,-727.36 U36.8@-204.11,-727.36
NetC197_2: C197.2 R150.2 U37.8 | length 142.9
  Bottom Layer w10: C197.2@-847.44,-23.54 -835.71,-11.81 R150.2@-793.31,-11.81 ; U37.8@-806.1,-91.17 -806.1,-26.45 -806.02,-26.37 -806.02,-20.59 -797.24,-11.81 R150.2@-796.32,-11.81
NetC205_2: C205.2 U41.3 | length 61.2
  Bottom Layer w10: U41.3@-1435.04,-1340.55 -1434.55,-1340.06 C205.2@-1434.55,-1279.53
NetC218_1: C218.1 U43.4 | length 114.8
  Bottom Layer w10: U43.4@-2378.15,-1066.93 -2373.51,-1071.57 -2373.51,-1118.62 -2341.46,-1150.67 -2341.46,-1162.48 C218.1@-2338.58,-1165.35
NetD1_1: D1.1 FL4.2 | length 186.3
  Top Layer w10: FL4.2@2933.07,-866.14 2933.46,-865.75 2933.46,-707.28 D1.1@2952.76,-687.99
NetD2_1: D2.1 FL1.2 | length 146.5
  Bottom Layer w10: D2.1@-349.41,-1279.53 -334.65,-1294.29 FL1.2@-334.65,-1417.32 ; D2.1@-334.65,-1281.9 cw(c-331.29,-1281.9) D2.1@-333.66,-1279.53
NetDS1_1: DS1.1 Q1.3 | length 139.2
  Top Layer w10: DS1.1@-1314.96,-464.57 -1193.9,-464.57 Q1.3@-1181.1,-477.36
NetDS1_2: DS1.2 R21.2 | length 76.6
  Top Layer w10: R21.2@-1322.83,-311.02 -1322.83,-351.44 -1321.77,-352.5 -1321.77,-357.36 -1304.13,-375 DS1.2@-1299.21,-375
NetDS2_2: DS2.2 R103.1 | length 90.8
  Bottom Layer w10: R103.1@3657.48,1488.19 3720.47,1488.19 DS2.2@3740.16,1507.87
NetDS3_1: DS3.1 Q5.3 | length 71.1
  Bottom Layer w10: Q5.3@3666.34,1929.13 3677.05,1918.43 3703.62,1918.43 DS3.1@3724.41,1897.64
NetDS3_2: DS3.2 R104.1 | length 96.1
  Bottom Layer w10: R104.1@3655.51,1751.97 3661.54,1757.99 3718.62,1757.99 DS3.2@3740.16,1779.53
NetJ2_12: J2.12 R56.2 U32.2 | length 295.7
  Top Layer w10: R56.2@1769.69,1810.75 1782.4,1798.03 J2.12@1948.82,1798.03
  Bottom Layer w10: U32.2@1779.72,1796.26 1780.61,1797.15 1887.7,1797.15 v1@1889.76,1799.21
  other v1: 1889.76,1798.03
NetJ2_13: J2.13 R55.2 U32.3 | length 308.5
  Top Layer w10: R55.2@1765.75,1732.28 1767.72,1732.28 1801.97,1766.54 J2.13@1948.82,1766.54
  Bottom Layer w10: U32.3@1779.72,1770.67 1781.79,1768.6 1885.26,1768.6 1886.15,1767.72 v1@1889.76,1767.72
  other v1: 1889.76,1766.54
NetJ2_18: J2.18 R53.1 U33.6 | length 303.7
  Top Layer w10: R53.1@1769.68,1633.86 1769.68,1629.92 1790.28,1609.33 1795.13,1609.33 1796.13,1608.33 1887.73,1608.33 v1@1889.76,1606.3 ; v1@1889.76,1608.17 1947.93,1608.17 J2.18@1948.82,1609.06
  Bottom Layer w10: U33.6@1779.33,1607.28 v1(1889.76,1607.28)
NetJ2_19: J2.19 R54.2 U33.7 | length 299.7
  Top Layer w10: R54.2@1769.69,1555.12 1769.69,1556.97 1790.28,1577.56 J2.19@1948.82,1577.56
  Bottom Layer w10: U33.7@1780.41,1579.63 1885.26,1579.63 1887.33,1577.56 v1(1889.76,1577.56)
NetJ5_1: J5.1 R102.2 R105.2 | length 324.5
  Top Layer w10: R102.2@3385.83,1147.64 3385.83,1145.59 3394.61,1136.81 3410.15,1136.81 3424.91,1122.05 J5.1@3602.36,1122.05
  Bottom Layer w10: R105.2@3507.87,1118.11 3511.81,1122.05 J5.1@3602.36,1122.05
NetP1_1: P1.1 R155.2 R158.2 R161.2 | length 790.9
  Bottom Layer w10: P1.1@-2233.46,853.94 -2196.22,816.69 ccw(c-2125.51,887.4) -2125.51,787.4 -1779.61,787.4 ccw(c-1779.61,887.4) -1708.9,816.69 -1670.2,855.39 -1668.23,855.39 -1657.48,866.14 -1657.48,868.11 R155.2@-1496.06,868.11
NetP1_3: P1.3 R165.2 R173.2 R178.2 | length 493.1
  Bottom Layer w10: P1.3@-2233.46,953.94 -2176.93,897.4 ccw(c-2106.22,968.11) -2106.22,868.11 R165.2@-1771.65,868.11
NetP1_5: P1.5 R166.2 R174.2 R179.2 | length 493.1
  Bottom Layer w10: P1.5@-2233.46,1053.94 -2176.93,1110.47 cw(c-2106.22,1039.76) -2106.22,1139.76 R166.2@-1771.65,1139.76
NetP1_7: P1.7 R156.2 R159.2 R162.2 | length 789.8
  Bottom Layer w10: P1.7@-2233.46,1153.94 -2196.22,1191.18 cw(c-2125.51,1120.47) -2125.51,1220.47 -1779.61,1220.47 cw(c-1779.61,1120.47) -1708.9,1191.18 -1670.2,1152.48 -1666.26,1152.48 -1653.54,1139.76 R156.2@-1496.06,1139.76
NetQ2_1: Q2.1 U21.7 | length 237.1
  Top Layer w9.31: 1118.61,-394.2 1142.92,-418.51
  Top Layer w10: Q2.1@1084.65,-275.59 1084.65,-277.56 1118.61,-311.52 1118.61,-394.2 ; 1142.92,-418.51 1153.35,-418.51 1173.23,-438.39 U21.7@1204.72,-438.39
NetQ2_2: Q2.2 R140.2 U21.6 | length 2103.2
  Top Layer w10: v2(1149.61,-362.2) 1149.61,-363.48 U21.6@1174.51,-388.39 ; Q2.2@1159.45,-275.59 1159.45,-277.56 1131.61,-305.4 1131.61,-389.3 1147.82,-405.51 1156.1,-405.51 1173.23,-388.39 U21.6@1174.51,-388.39 ; U21.6@1204.72,-388.39 U21.6@1174.51,-388.39
  Bottom Layer w10: R140.2@-118.11,-1242.13 ccw(c-118.11,-1218.5) -94.49,-1218.5 -94.49,-1188.96 cw(c-15.39,-1188.96) -15.39,-1109.86 221.26,-1109.86 ccw(c221.26,-1032.41) 298.71,-1032.41 298.71,-959.75 cw(c431.69,-959.75) 431.69,-826.77 801.1,-826.77 ccw(c801.1,-726.77) 871.81,-797.48 1159.69,-509.6 ccw(c1088.98,-438.89) 1188.98,-438.89 1188.98,-429.13 ccw(c1122.44,-429.13) 1169.49,-382.09 v2(1149.61,-362.2)
NetQ3_1: Q3.1 U21.1 | length 299.1
  Top Layer w10: Q3.1@1261.81,-275.59 1261.81,-277.56 1293.63,-309.38 1293.63,-442.34 1315.02,-463.73 1335.18,-463.73 1359.84,-488.39 U21.1@1393.7,-488.39
NetQ3_2: Q3.2 R46.1 U21.2 | length 408.4
  Top Layer w10: Q3.2@1336.61,-275.59 1336.61,-277.56 1306.63,-307.54 1306.63,-436.96 1319.93,-450.26 1346.8,-450.26 1358.67,-438.39 U21.2@1393.7,-438.39 1396.26,-440.94 1484.25,-440.94 1500,-456.69 R46.1@1501.97,-456.69 ; R46.1@1483.66,-442.32 1485.32,-442.32 1498.03,-455.04 R46.1@1498.03,-456.69
NetQ4_2: Q4.2 R93.1 U26.29 | length 399.4
  Top Layer w10: Q4.2@2546.8,-1235.3 2578.05,-1235.3 2578.76,-1234.58 v4@2579.66,-1234.58 ; v4@2579.69,-1234.56 R93.1@2608.27,-1234.56
  Int2 (Sign) w10: v4(2241.14,-1230.31) v4(2578.74,-1234.97)
NetQ4_4: Q4.4 R94.1 U26.31 | length 409.6
  Top Layer w10: Q4.4@2540.81,-1135.72 2578.47,-1135.72 2578.74,-1135.45 R94.1@2608.25,-1135.45
  Int2 (Sign) w10: v4(2241.14,-1190.94) v4(2578.74,-1135.82)
NetQ6_1: Q6.1 U35.5 | length 159.1
  Bottom Layer w10: Q6.1@946.85,-1471.46 946.85,-1470.47 1002.24,-1415.09 ccw(c966.95,-1379.8) 1016.85,-1379.8 1016.85,-1362.13 1022.68,-1356.3 U35.5@1037.4,-1356.3
NetQ6_3: Q6.3 R37.1 U19.7 | length 185.6
  Top Layer w10: R37.1@1009.84,-1692.91 1009.84,-1586.02 1016.06,-1579.8 1017.25,-1579.8 1023.62,-1573.43 v2(1023.62,-1555.12)
  Bottom Layer w10: Q6.3@984.25,-1560.04 1015.99,-1560.04 1020.92,-1555.12 v2(1023.62,-1555.12)
NetR2_1: R2.1 R8.2 U3.6 | length 494.5
  Top Layer w10: R2.1@-2451.02,-1530.12 -2129.92,-1530.12 -2104.33,-1555.71 R8.2@-2104.33,-1692.91
NetR5_1: R5.1 U1.6 | length 120.1
  Top Layer w10: R5.1@-2271.65,-299.21 -2244.23,-326.64 cw(c-2275.44,-357.85) -2231.3,-357.85 U1.6@-2231.3,-404.53
NetR6_1: R6.1 U5.6 | length 127.8
  Top Layer w10: R6.1@-2120.08,-295.28 -2118.11,-295.28 -2085.69,-327.69 cw(c-2114.37,-356.36) -2073.82,-356.36 U5.6@-2073.82,-404.53
NetR7_1: R7.1 R11.2 U4.1 | length 409.5
  Top Layer w10: R7.1@-2029.53,-1023.62 -2029.53,-1230.51 -2004.13,-1255.91 U4.1@-1968.5,-1255.91 ; U4.1@-1972.44,-1256.1 -1940.94,-1256.1 -1910.63,-1286.42 -1855.31,-1286.42 R11.2@-1854.33,-1285.43
NetR8_1: R8.1 R9.2 U3.2 | length 356.8
  Top Layer w10: R9.2@-2099.96,-1417.75 -2099.96,-1484.09 -2003.94,-1580.12 U3.2@-1972.44,-1580.12 ; R8.1@-2029.53,-1692.91 -2029.53,-1605.14 U3.2@-2004.51,-1580.12
NetR10_1: R10.1 U6.6 | length 122.7
  Top Layer w10: U6.6@-1913.39,-409.45 -1913.32,-409.39 -1913.32,-310.96 -1897.64,-295.28 R10.1@-1895.67,-295.28
NetR11_1: R11.1 R13.2 U4.2 | length 225
  Top Layer w10: U4.2@-1972.44,-1206.1 -1916.14,-1206.1 -1887.99,-1234.25 -1816.93,-1234.25 -1791.34,-1259.84 R13.2@-1769.69,-1259.84
NetR12_1: R12.1 U8.6 | length 106.9
  Top Layer w10: U8.6@-1755.91,-393.7 -1755.84,-393.64 -1755.84,-310.96 -1740.16,-295.28 R12.1@-1738.19,-295.28
NetR14_1: R14.1 U12.4 | length 183.2
  Top Layer w10: R14.1@-1710.63,-1181.1 -1706.69,-1181.1 -1668.31,-1219.49 U12.4@-1543.31,-1219.49
NetR15_1: R15.1 U11.4 | length 221.5
  Top Layer w10: R15.1@-1764.76,-1593.5 U11.4@-1543.31,-1593.5
NetR16_2: R16.2 R18.1 R19.1 U9.2 U9.5 | length 452.9
  Top Layer w10: U9.2@-1662.4,-148.62 -1615.16,-148.62 cw(c-1615.16,-186.64) -1588.27,-159.76 -1569.8,-178.23 ccw(c-1517.72,-126.14) -1517.72,-199.8 -1420.28,-199.8 R19.1@-1417.32,-196.85 ; R16.2@-1633.86,-261.81 R18.1@-1515.75,-261.81 ; R18.1@-1515.75,-259.84 -1484.25,-228.35 U9.5@-1484.25,-200.79
NetR17_1: R17.1 U9.8 | length 82
  Top Layer w10: R17.1@-1535.43,-70.87 -1507.83,-98.47 -1507.83,-119.17 -1503.97,-123.03 U9.8@-1487.2,-123.03
NetR17_2: R17.2 U9.1 | length 87.5
  Top Layer w10: U9.1@-1662.4,-123.03 -1645.63,-123.03 -1641.78,-119.17 -1641.78,-98.47 R17.2@-1610.24,-66.93
NetR19_2: R19.2 R24.1 U9.6 | length 289.8
  Top Layer w10: U9.6@-1487.2,-174.21 -1483.35,-170.35 -1461.69,-170.35 -1435.94,-144.61 -1432.01,-144.61 -1421.26,-133.86 R19.2@-1421.26,-129.92 ; R19.2@-1417.32,-127.95 -1222.44,-127.95 R24.1@-1216.54,-133.86
NetR30_1: R30.1 R33.1 U18.9 U20.3 | length 547.2
  Top Layer w10: R30.1@669.29,1097.36 683.98,1112.05 689.88,1112.05 824.87,1247.03 R33.1@824.87,1267.58 ; R33.1@826.77,1279.53 826.77,1269.49 R33.1@824.87,1267.58 ; U20.3@1077.36,1273.23 1077.36,1279.55 1074.71,1282.2 1074.17,1282.2 1037.47,1318.9 988.39,1318.9 946.85,1277.36 834.65,1277.36 R33.1@824.87,1267.58
NetR31_1: R31.1 R44.1 U18.8 U20.2 | length 737.1
  Top Layer w10: R31.1@748.03,1097.74 763.2,1112.91 769.11,1112.91 857.66,1201.46 962.48,1201.46 1000.14,1239.11 1099.02,1239.11 1122.39,1262.48 1122.93,1262.48 1127.36,1266.91 1127.36,1279.55 1131.79,1283.98 1132.33,1283.98 1167.25,1318.9 1216.34,1318.9 1257.87,1277.36 R44.1@1368.89,1277.36
NetR32_1: R32.1 R35.1 U18.15 U20.5 | length 249.5
  Top Layer w10: R35.1@830.71,1029.88 830.71,985.24 R32.1@838.58,977.36 1024.71,977.36 1027.36,974.71 U20.5@1027.36,970.87
NetR34_2: R34.2 R36.1 U16.L12 U18.16 U20.6 | length 2017.3
  Top Layer w10: v1(-39.37,39.37) U16.L12@-19.69,19.69 ; R34.2@838.58,927.36 v1(1053.15,927.36) ; R36.1@1053.15,866.14 v1(1053.15,927.36) ; U20.6@1077.36,970.87 1075.48,968.99 1075.48,961.11 1054.76,940.39 1054.76,928.98 v1(1053.15,927.36)
  Int2 (Sign) w8.15: 740.59,898.07 cw(c811.3,827.36) 811.3,927.36
  Int2 (Sign) w8.59: 295.28,411.33 cw(c395.28,411.33) 324.56,482.05
  Int2 (Sign) w10: v1(-39.37,39.37) cw(c-19.69,39.37) -19.69,59.06 236.22,59.06 ccw(c236.22,118.11) 295.28,118.11 295.28,411.33 ; 324.56,482.05 360.48,517.96 740.59,898.07 ; 811.3,927.36 v1(1053.15,927.36)
NetR39_1: R39.1 R40.1 U18.1 U20.7 | length 312.9
  Top Layer w10: R39.1@1102.36,879.92 1110.72,888.28 1110.72,910.72 1127.36,927.36 ; R39.1@1102.36,880.83 1117.05,866.14 R40.1@1151.77,866.14 ; U20.7@1127.36,970.87 1127.36,927.36 ; U18.1@1283.46,927.36 1127.36,927.36
NetR43_1: R43.1 U18.3 | length 85.4
  Top Layer w10: U18.3@1283.46,1027.36 R43.1@1368.89,1027.36
NetR47_1: R47.1 U21.3 | length 137.1
  Top Layer w10: U21.3@1393.7,-388.39 1396.26,-385.83 1479.46,-385.83 1480.52,-384.76 1487.28,-384.76 R47.1@1501.97,-370.08 ; R47.1@1483.66,-384.45 1485.32,-384.45 1498.03,-371.73 R47.1@1498.03,-370.08
NetR50_1: R50.1 U23.9 U25.2 | length 569.3
  Top Layer w10: U23.9@1248.03,284.45 1248.03,236.72 1268.21,216.54 1377.95,216.54 1456.69,295.28 1574.8,295.28 ; U25.2@1574.8,340.55 1574.8,295.28 ; R50.1@1675.2,275.59 1594.49,275.59 1574.8,295.28
NetR51_1: R51.1 U23.5 U25.1 | length 836.9
  Top Layer w10: U23.5@1273.62,502.95 1273.62,562.99 cw(c1301.18,562.99) 1301.18,590.55 R51.1@1687.01,590.55 1686.52,590.06 1686.52,446.36 1633.86,393.7 1572.83,393.7 1537.4,358.27 U25.1@1537.4,340.55
NetR52_1: R52.1 R58.1 U26.6 | length 355.2
  Top Layer w10: R52.1@1687.01,-1262.96 1685.04,-1260.99 1685.04,-1215.47 1689.88,-1210.63 R58.1@1692.91,-1210.63 ; v4(1948.82,-1190.93) U26.6@1961.69,-1190.93
  Int2 (Sign) w10: v4(1685.04,-1240.16) 1767.72,-1240.16 1816.94,-1190.93 v4(1948.82,-1190.93)
NetR61_1: R61.1 R73.2 U26.17 | length 468.6
  Top Layer w10: R61.1@1986.22,-1692.91 2017.18,-1692.91 2046.71,-1663.39 v4(2047.24,-1663.39) 2047.24,-1662.85 2076.83,-1633.26 2076.83,-1626.84 2077.83,-1625.84 2077.83,-1619.02 R73.2@2086.61,-1610.24 ; v4(2076.77,-1358.26) U26.17@2076.77,-1345.39
  Bottom Layer w10: v4(2047.24,-1663.39) ccw(c1999.72,-1615.86) 2066.93,-1615.86 2066.93,-1382.02 cw(c2100.53,-1382.02) v4(2076.77,-1358.26)
NetR62_2: R62.2 R63.2 R71.1 U26.13 | length 369.2
  Top Layer w10: R62.2@1980.81,-1641.5 1984.31,-1645 cw(c1979.71,-1649.61) R62.2@1986.22,-1649.61 R63.2@1986.22,-1608.27 ; R63.2@1988.19,-1606.3 1990.16,-1604.33 R71.1@2045.28,-1604.33 ; v4@1998,-1358.23 U26.13@1998,-1345.39
  Int2 (Sign) w10: v4(1997.97,-1358.26) v4(2019.68,-1604.33)
NetR65_2: R65.2 U26.15 | length 83.1
  Top Layer w10: R65.2@1984.19,-1386.8 2017.78,-1386.8 2037.4,-1367.18 U26.15@2037.4,-1345.39
NetR66_2: R66.2 U26.46 | length 53.6
  Top Layer w10: R66.2@2019.68,-1009.84 2028.46,-1018.62 2028.46,-1033.33 2031.65,-1036.51 2031.65,-1050.51 U26.46@2037.32,-1056.18
NetR67_1: R67.1 R69.1 U26.16 | length 169.6
  Top Layer w10: R69.1@2033.47,-1437.02 2066.99,-1470.54 2066.99,-1473.55 2067.99,-1474.55 2067.99,-1479.41 2069.87,-1481.29 R67.1@2078.74,-1481.29 ; R69.1@2033.47,-1437 2057.09,-1413.39 U26.16@2057.09,-1345.39
NetR68_1: R68.1 R70.1 U26.45 | length 252.4
  Top Layer w10: R70.1@2042.24,-914.29 2033.96,-906 2033.96,-905.02 2042.24,-896.73 R70.1@2043.49,-896.73 ; U26.45@2057.09,-1065.94 2057.09,-1042.81 2043.49,-1029.21 R70.1@2043.49,-896.73 ; R68.1@2082.68,-866.13 2073.89,-874.92 2067,-874.92 2045.19,-896.73 R70.1@2043.49,-896.73
NetR74_1: R74.1 R83.2 R84.2 U26.18 | length 517.5
  Top Layer w10: v4@2096.49,-1358.23 U26.18@2096.49,-1345.39 ; R74.1@2133.86,-1618.11 2134.76,-1619.02 2134.76,-1625.84 2135.76,-1626.84 2135.76,-1633.8 2194.88,-1692.91 R83.2@2230.31,-1692.91 2232.28,-1690.94 R84.2@2232.28,-1649.61
  Bottom Layer w10: v4(2096.52,-1358.26) 2096.52,-1383.87 ccw(c2129.91,-1383.87) 2106.3,-1407.48 2116.38,-1417.56 cw(c2045.67,-1488.27) 2145.67,-1488.27 2145.67,-1615.86 ccw(c2212.88,-1615.86) v4(2165.35,-1663.39)
NetR75_1: R75.1 R77.1 U26.21 | length 191.7
  Top Layer w10: R77.1@2131.89,-1488.19 2135.83,-1488.19 2144.61,-1479.41 2144.61,-1474.55 2145.61,-1473.55 2145.61,-1470.54 R75.1@2179.13,-1437.01 ; U26.21@2155.51,-1345.39 2155.51,-1413.38 R75.1@2179.12,-1437 ; R75.1@2174.77,-1427.22 R75.1@2182.09,-1434.54 ; R75.1@2182.09,-1437 R75.1@2179.12,-1437 ; R75.1@2183.07,-1437.01 R75.1@2179.13,-1437.01
NetR76_1: R76.1 R78.1 U26.40 | length 231.4
  Top Layer w10: R78.1@2135.82,-866.13 2145.6,-875.91 2146.65,-875.91 2167.47,-896.73 2170.35,-896.73 2176.7,-903.08 R76.1@2176.7,-905.96 ; U26.40@2155.51,-1056.18 2155.51,-1040.46 2165.94,-1030.03 R76.1@2165.94,-896.73 ; R76.1@2176.7,-907.94 R76.1@2176.7,-905.96 ; R76.1@2183.07,-905.51 2177.15,-905.51 R76.1@2176.7,-905.96
NetR80_1: R80.1 U26.41 | length 43.4
  Top Layer w10: U26.41@2135.83,-1056.18 2135.83,-1019.48 R80.1@2140.55,-1014.75
NetR81_1: R81.1 R85.2 R117.2 U26.19 | length 381.6
  Top Layer w10: v4(2116.14,-1358.26) U26.19@2116.14,-1345.39 ; R81.1@2165.35,-1613.11 2174.13,-1604.33 2226.38,-1604.33 R85.2@2228.35,-1606.3
  Bottom Layer w10: v4(2116.14,-1358.26) 2116.14,-1367.97 ccw(c2149.75,-1367.97) 2125.98,-1391.73 2167.56,-1433.31 cw(c2096.85,-1504.02) 2196.85,-1504.02 v4(2196.85,-1604.33) R117.2@2224.41,-1604.33
NetR82_2: R82.2 U26.39 | length 58.5
  Top Layer w10: U26.39@2175.27,-1056.18 2180.38,-1051.07 2180.38,-1026.31 2195.23,-1011.46 R82.2@2195.23,-1005.96
NetR86_2: R86.2 U26.22 | length 84
  Top Layer w10: U26.22@2175.2,-1345.39 2175.2,-1367.12 2194.88,-1386.8 R86.2@2229.33,-1386.8
NetR87_1: R87.1 R95.2 | length 811.1
  Top Layer w10: R87.1@2476.38,476.38 2480.32,472.44 2537.8,472.44 cw(c2537.8,372.44) 2637.8,372.44 R95.2@2637.8,-218.5
NetR88_2: R88.2 R89.1 U28.6 | length 273
  Top Layer w10: U28.6@2279.53,408.07 2280.91,406.69 2327.56,406.69 2398.7,335.55 2398.7,331.61 2407.48,322.83 2415.35,322.83 2424.13,314.06 2424.13,310.12 2456.75,277.5 2456.75,252.87 R88.2@2465.53,244.09
NetR100_1: R100.1 T1.3 U29.3 | length 205.1
  Top Layer w10: U29.3@2882.09,1134.84 2883.07,1133.86 2933.07,1133.86 2940.94,1141.73 2957.76,1141.73 2971.46,1155.43 R100.1@2971.46,1156.5 ; R100.1@2972.44,1155.51 2982.28,1165.35 3064.17,1165.35 T1.3@3070.87,1172.05
NetR100_2: R100.2 T1.1 U29.2 | length 191.4
  Top Layer w10: U29.2@2882.09,1109.25 2934.06,1109.25 2940.94,1102.36 R100.2@2965.39,1102.36 ; R100.2@2972.44,1088.58 2982.28,1078.74 3064.17,1078.74 T1.1@3070.87,1072.05
NetR101_2: R101.2 R102.1 T1.6 TP26.1 | length 335.6
  Top Layer w10: TP26.1@3129.92,964.57 3196.85,1031.5 T1.6@3196.85,1070.87 ; T1.6@3195.87,1072.05 3351.38,1072.05 3364.45,1085.12 3377.05,1085.12 3385.83,1093.9 R102.1@3385.83,1096.46
NetR109_1: R109.1 R115.2 U26.5 U26.37 | length 554.8
  Top Layer w10: v4(1948.82,-1171.25) U26.5@1961.69,-1171.25 ; U26.37@2214.57,-1056.18 2214.57,-1046.94 2220.47,-1041.03 v4(2220.47,-1040.49)
  Int2 (Sign) w10: v4(1948.82,-1171.25) 1948.82,-1082.68 cw(c2007.87,-1082.68) 2007.87,-1023.62 2203.6,-1023.62 cw(c2203.6,-1040.49) v4(2220.47,-1040.49)
  Bottom Layer w10: v4(2220.47,-1040.49) 2257.74,-1040.49 2270.75,-1027.48 2270.75,-1018.62 R115.2@2279.53,-1009.84 R109.1@2322.83,-1009.84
